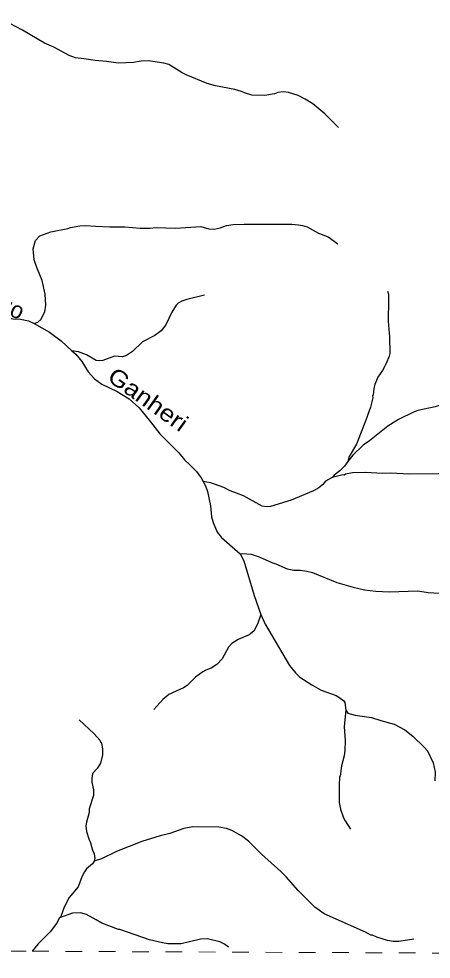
# Model space of a CAD drawing. Extents: x 551.6 to 577.6, y 7567 to 7594.7.
# Drawn here: x 566.69 to 569.17, y 7566.95 to 7572.59 of the extents above; entities that cross this region are included whole.
import ezdxf
from ezdxf.enums import TextEntityAlignment as Align

# ---------------------------------------------------------------- set-up
doc = ezdxf.new("R2010")
doc.units = 0
doc.header["$LTSCALE"] = 0.04
doc.linetypes.add('SHORT_DASHED', pattern=[2.7, 1.5, -1.2])
doc.layers.add('53', color=7, linetype='SHORT_DASHED', lineweight=13)
doc.layers.add('7', color=7, linetype='Continuous', lineweight=25)
doc.layers.add('61', color=7, linetype='Continuous')

msp = doc.modelspace()

# ---------------------------------------------------------------- linework, layer by layer
at = {"layer": '53'}
msp.add_lwpolyline([(551.613, 7567.0572), (552.9162, 7567.0524), (553.7221, 7567.0495), (554.9107, 7567.0451), (556.1477, 7567.0406), (557.2075, 7567.0367), (559.4055, 7567.0287), (559.6981, 7567.0276), (560.556, 7567.0244), (562.9715, 7567.0156), (564.6334, 7567.0092), (566.4358, 7567.0011), (566.7714, 7566.9996), (570.8595, 7566.9812), (572.5416, 7566.9737), (572.8363, 7566.9724), (573.5039, 7566.9694), (573.609, 7566.9689), (574.6855, 7566.9641), (575.0536, 7566.9624), (576.5544, 7566.9557), (577.1266, 7566.9531), (577.4204, 7566.9518)], dxfattribs=at)
at = {"layer": '7'}
for points in [[(567.6241, 7572.3002), (567.5903, 7572.3195), (567.5614, 7572.3284), (567.4696, 7572.3413), (567.4245, 7572.3397), (567.3795, 7572.3316), (567.2877, 7572.3284), (567.2169, 7572.3381), (567.1493, 7572.3429), (567.0817, 7572.3542), (567.0318, 7572.359), (566.9932, 7572.3735), (566.9014, 7572.4234), (566.8451, 7572.4483), (566.7123, 7572.5264), (566.6374, 7572.565), (566.536, 7572.594)], [(568.61, 7571.9413), (568.5271, 7572.0242), (568.4547, 7572.0829), (568.4096, 7572.1119), (568.3677, 7572.1336), (568.3098, 7572.1513), (568.2792, 7572.1554), (568.2462, 7572.1513), (568.2245, 7572.1441), (568.1666, 7572.1336), (568.0901, 7572.1361), (568.0458, 7572.1489), (568.0265, 7572.1586), (567.9879, 7572.1707), (567.8704, 7572.1916), (567.8221, 7572.206), (567.6957, 7572.2576), (567.6708, 7572.2696), (567.6241, 7572.3002)], [(566.7829, 7570.7658), (566.8056, 7570.7735), (566.8233, 7570.7904), (566.8467, 7570.8363), (566.8531, 7570.8766), (566.8483, 7570.9409), (566.8314, 7571.0246), (566.7984, 7571.1019), (566.7823, 7571.1486), (566.7775, 7571.2146), (566.7903, 7571.2629), (566.8177, 7571.291), (566.8821, 7571.3151), (566.9851, 7571.3361), (567.0012, 7571.3425), (567.0575, 7571.3522), (567.093, 7571.3538), (567.1509, 7571.3506)], [(567.1509, 7571.3506), (567.2378, 7571.3457), (567.3264, 7571.3457), (567.4197, 7571.3385), (567.4777, 7571.3385), (567.5147, 7571.3425), (567.6306, 7571.3385), (567.7835, 7571.3473), (567.8318, 7571.3345), (567.864, 7571.3312), (567.8994, 7571.3393), (567.938, 7571.353), (567.9766, 7571.3602), (568.0442, 7571.361)], [(568.0442, 7571.361), (568.3291, 7571.361), (568.3694, 7571.3586), (568.3935, 7571.3538), (568.4217, 7571.3457), (568.4892, 7571.3071), (568.5464, 7571.2854), (568.6052, 7571.2443)], [(567.8052, 7570.9353), (567.6982, 7570.9103), (567.6692, 7570.8999), (567.6466, 7570.887), (567.6354, 7570.8749), (567.6096, 7570.8331), (567.5726, 7570.7574), (567.5444, 7570.7228), (567.53, 7570.7091), (567.5066, 7570.6938), (567.4326, 7570.656), (567.3738, 7570.5973), (567.3376, 7570.5731), (567.3135, 7570.5659), (567.2652, 7570.5707), (567.1944, 7570.5442), (567.175, 7570.5409), (567.1557, 7570.5442), (567.0978, 7570.578), (567.0495, 7570.5957), (567.009, 7570.6018)], [(568.9029, 7570.9594), (568.9086, 7570.9409), (568.9102, 7570.9087), (568.907, 7570.78), (568.915, 7570.6834), (568.9166, 7570.5868), (568.9134, 7570.5707), (568.8957, 7570.5265), (568.8732, 7570.4838), (568.845, 7570.4436), (568.8265, 7570.4001), (568.8208, 7570.376), (568.8168, 7570.3357), (568.8136, 7570.3325), (568.8152, 7570.3196), (568.812, 7570.3035), (568.8015, 7570.2633), (568.7742, 7570.186)], [(566.5127, 7570.8435), (566.5537, 7570.821), (566.6101, 7570.8041), (566.6551, 7570.7944), (566.7002, 7570.7928), (566.7485, 7570.7816), (566.7829, 7570.7658)], [(566.7829, 7570.7658), (566.8748, 7570.7148), (566.9449, 7570.6617), (567.009, 7570.6018)], [(567.009, 7570.6018), (567.0334, 7570.5812), (567.0696, 7570.5369), (567.1074, 7570.4758), (567.1445, 7570.4347), (567.1895, 7570.4025), (567.2805, 7570.3582), (567.3537, 7570.3148), (567.4124, 7570.2601), (567.4817, 7570.1756)], [(569.7609, 7570.6118), (569.7021, 7570.5715), (569.6112, 7570.4902), (569.509, 7570.4057), (569.4188, 7570.3574), (569.3947, 7570.3389), (569.3045, 7570.3019), (569.1887, 7570.2657), (569.0856, 7570.244), (569.0599, 7570.2343), (568.9698, 7570.19), (568.9054, 7570.1498), (568.7959, 7570.0621), (568.7581, 7570.0355), (568.6945, 7569.976), (568.6659, 7569.9382)], [(567.4817, 7570.1756), (567.5364, 7570.1039), (567.6507, 7569.9905), (567.6853, 7569.9478), (567.7175, 7569.9188), (567.7569, 7569.877), (567.7843, 7569.84), (567.7968, 7569.8173)], [(568.7742, 7570.186), (568.717, 7570.0428), (568.6736, 7569.9679), (568.6659, 7569.9382)], [(568.6659, 7569.9382), (568.6446, 7569.91), (568.618, 7569.8826)], [(569.6812, 7569.9462), (569.6442, 7569.9317), (569.5959, 7569.9196), (569.4897, 7569.914), (569.4655, 7569.9059), (569.3239, 7569.8882), (569.2756, 7569.8746), (569.2096, 7569.8641), (569.0325, 7569.8617), (568.9231, 7569.8673), (568.8748, 7569.8657), (568.7702, 7569.8721)], [(568.618, 7569.8826), (568.5843, 7569.8561), (568.5722, 7569.8424)], [(568.7702, 7569.8721), (568.6929, 7569.8705), (568.6511, 7569.8625), (568.643, 7569.8561), (568.635, 7569.8569), (568.5722, 7569.8424)], [(567.9976, 7569.7482), (567.9589, 7569.7627), (567.9203, 7569.782), (567.8656, 7569.8013), (567.8414, 7569.8094), (567.7968, 7569.8173)], [(567.7968, 7569.8173), (567.8108, 7569.7917), (567.8237, 7569.7579), (567.8414, 7569.671), (567.8478, 7569.6066), (567.8575, 7569.5728), (567.8816, 7569.5148), (567.9074, 7569.4818), (568.0183, 7569.3835)], [(568.5722, 7569.8424), (568.5319, 7569.8206), (568.515, 7569.8005), (568.4909, 7569.7804), (568.4587, 7569.7611), (568.3259, 7569.7064), (568.2004, 7569.6677), (568.181, 7569.6669), (568.1521, 7569.6709), (568.0394, 7569.7321), (567.9976, 7569.7482)], [(568.0183, 7569.3835), (568.0346, 7569.3868), (568.0845, 7569.3812), (568.1328, 7569.3667), (568.21, 7569.3313), (568.2326, 7569.3249)], [(568.0183, 7569.3835), (568.0418, 7569.341), (568.103, 7569.1334), (568.1441, 7569.0203)], [(568.2326, 7569.3249), (568.3018, 7569.2943), (568.342, 7569.2863), (568.3806, 7569.2855), (568.4193, 7569.2806), (568.4531, 7569.2726), (568.5995, 7569.2122), (568.6977, 7569.1832), (568.7653, 7569.1688), (568.8329, 7569.1599), (568.9134, 7569.1559), (569.0856, 7569.1623), (569.1484, 7569.1527), (569.216, 7569.147), (569.2386, 7569.143), (569.2836, 7569.1285)], [(568.1441, 7569.0203), (568.1223, 7568.9611), (568.1022, 7568.9209), (568.074, 7568.8975), (568.0072, 7568.8702), (567.9686, 7568.8468), (567.9484, 7568.8243), (567.9106, 7568.7543), (567.8801, 7568.7205), (567.8446, 7568.6979), (567.8124, 7568.6859), (567.7947, 7568.6754), (567.7521, 7568.6432), (567.7014, 7568.5949), (567.6789, 7568.5804), (567.5919, 7568.5394), (567.5557, 7568.5104), (567.501, 7568.4501)], [(568.1441, 7569.0203), (568.169, 7568.9611), (568.3162, 7568.7149), (568.3508, 7568.6706), (568.3782, 7568.6448), (568.4499, 7568.5981), (568.5046, 7568.5668), (568.5947, 7568.533), (568.6108, 7568.5249), (568.6414, 7568.5024), (568.6478, 7568.4927), (568.654, 7568.4453)], [(568.654, 7568.4453), (568.6438, 7568.3479), (568.6486, 7568.2626), (568.6478, 7568.2062), (568.643, 7568.1724), (568.6269, 7568.1113), (568.6188, 7568.0493), (568.6156, 7568.0453), (568.6124, 7567.9938), (568.614, 7567.8924), (568.6204, 7567.8521), (568.6398, 7567.7998), (568.6486, 7567.7813), (568.6808, 7567.7322)], [(568.654, 7568.4453), (568.6659, 7568.4282), (568.7084, 7568.4163), (568.8072, 7568.401), (568.8635, 7568.3833)], [(567.0535, 7568.3873), (567.142, 7568.3044), (567.1766, 7568.2658), (567.1823, 7568.2521), (567.1863, 7568.2497), (567.1927, 7568.2127), (567.1927, 7568.1789), (567.1815, 7568.1274), (567.1606, 7568.096), (567.1332, 7568.0662), (567.1284, 7568.0356), (567.1284, 7568.0131), (567.138, 7567.968), (567.138, 7567.9342), (567.1139, 7567.8537), (567.1123, 7567.8312), (567.0962, 7567.7749), (567.0929, 7567.7523), (567.0978, 7567.7185), (567.1106, 7567.6735), (567.1219, 7567.6509), (567.1332, 7567.6059), (567.142, 7567.5849), (567.1469, 7567.556), (567.1431, 7567.5406)], [(568.8635, 7568.3833), (568.944, 7568.3623), (569.0084, 7568.3277), (569.055, 7568.2899), (569.1243, 7568.2247), (569.1436, 7568.2014), (569.1774, 7568.129), (569.1902, 7568.0742), (569.1885, 7568.0219)], [(568.0281, 7567.6919), (567.9702, 7567.7249), (567.9364, 7567.7354), (567.8913, 7567.7434), (567.7352, 7567.7459), (567.6821, 7567.7362), (567.5968, 7567.7056), (567.5388, 7567.6911), (567.4294, 7567.6573), (567.2765, 7567.5978), (567.1863, 7567.5543), (567.1431, 7567.5406)], [(569.0607, 7567.0715), (568.9714, 7567.057), (568.9376, 7567.0578), (568.9038, 7567.0642), (568.8394, 7567.0843), (568.8136, 7567.0964), (568.8031, 7567.0964), (568.7718, 7567.1133), (568.5239, 7567.2235), (568.4683, 7567.2638), (568.3677, 7567.3636), (568.2961, 7567.4465), (568.2639, 7567.4787), (568.148, 7567.5825), (568.0692, 7567.6598), (568.0281, 7567.6919)], [(567.1431, 7567.5406), (567.1334, 7567.5234), (567.0978, 7567.4932), (567.0849, 7567.4755)], [(567.0849, 7567.4755), (567.0688, 7567.4457), (567.0479, 7567.3869), (566.9932, 7567.3225), (566.9626, 7567.2646), (566.9432, 7567.2083), (566.9354, 7567.2)], [(567.1541, 7567.1881), (567.0978, 7567.2203), (567.0608, 7567.2308), (567.0125, 7567.2276), (566.9354, 7567.2)], [(566.9354, 7567.2), (566.9167, 7567.1664), (566.8797, 7567.1165), (566.8064, 7567.0441), (566.7714, 7566.9996)], [(567.9485, 7567.0232), (567.9251, 7567.0425), (567.8978, 7567.0562), (567.8237, 7567.0747), (567.7819, 7567.0723), (567.666, 7567.0441), (567.5855, 7567.0449), (567.5533, 7567.0505), (567.476, 7567.0682), (567.2974, 7567.1294), (567.2893, 7567.1294), (567.1895, 7567.1672), (567.1541, 7567.1881)]]:
    msp.add_lwpolyline(points, dxfattribs=at)

# ---------------------------------------------------------------- texts
at = {"layer": '61'}
msp.add_text('Córrego', height=0.1, rotation=334.925, dxfattribs=at).set_placement((566.4764, 7570.888), align=Align.CENTER)
at = {"layer": '61', "width": 1.15}
msp.add_text('Ganheri', height=0.1, rotation=324.546, dxfattribs=at).set_placement((567.4376, 7570.2699), align=Align.CENTER)

doc.saveas('drawing.dxf')
